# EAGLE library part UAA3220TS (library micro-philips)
FSK / ASK Receiver Frequency Shift Keying / Amplitude Shift Keying
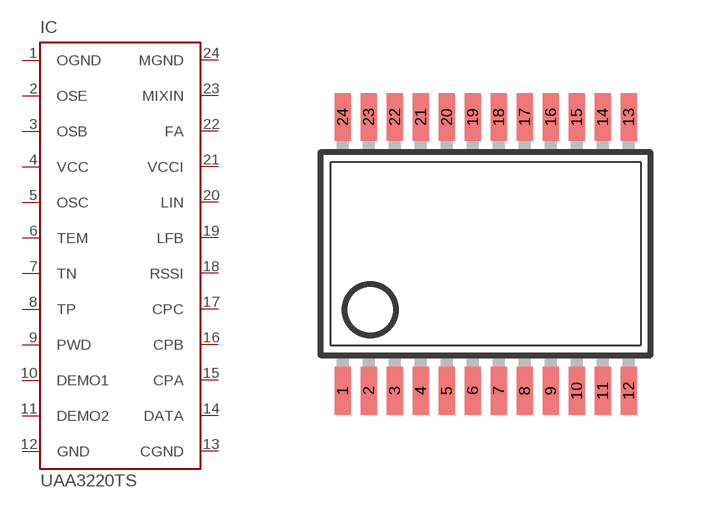
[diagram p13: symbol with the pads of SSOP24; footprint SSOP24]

Designator prefix IC

## UAA3220TS (MPN: UAA3220TS/V1,118; OC_FARNELL: unknown; OC_NEWARK: 70R9521)  [SSOP24]
1  OGND  pwr
2  OSE  pas
3  OSB  pas
4  VCC  pwr
5  OSC  oc
6  TEM  pas
7  TN  oc
8  TP  oc
9  PWD  pas
10  DEMO1  pas
11  DEMO2  pas
12  GND  pwr
13  CGND  pwr
14  DATA  pas
15  CPA  pas
16  CPB  pas
17  CPC  pas
18  RSSI  pas
19  LFB  pas
20  LIN  pas
21  VCCI  pwr
22  FA  pas
23  MIXIN  pas
24  MGND  pas

## Footprint SSOP24 (pad centres in mm)
Small Shrink Outline Package SOT340-1 / JEDEC MO-150AG
smd 0.4 x 1.2: 1 -3.575,-3.42; 2 -2.925,-3.42; 3 -2.275,-3.42; 4 -1.625,-3.42; 5 -0.975,-3.42; 6 -0.325,-3.42; 7 0.325,-3.42; 8 0.975,-3.42; 9 1.625,-3.42; 10 2.275,-3.42; 11 2.925,-3.42; 12 3.575,-3.42; 13 3.575,3.42; 14 2.925,3.42; 15 2.275,3.42; 16 1.625,3.42; 17 0.975,3.42; 18 0.325,3.42; 19 -0.325,3.42; 20 -0.975,3.42; 21 -1.625,3.42; 22 -2.275,3.42; 23 -2.925,3.42; 24 -3.575,3.42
